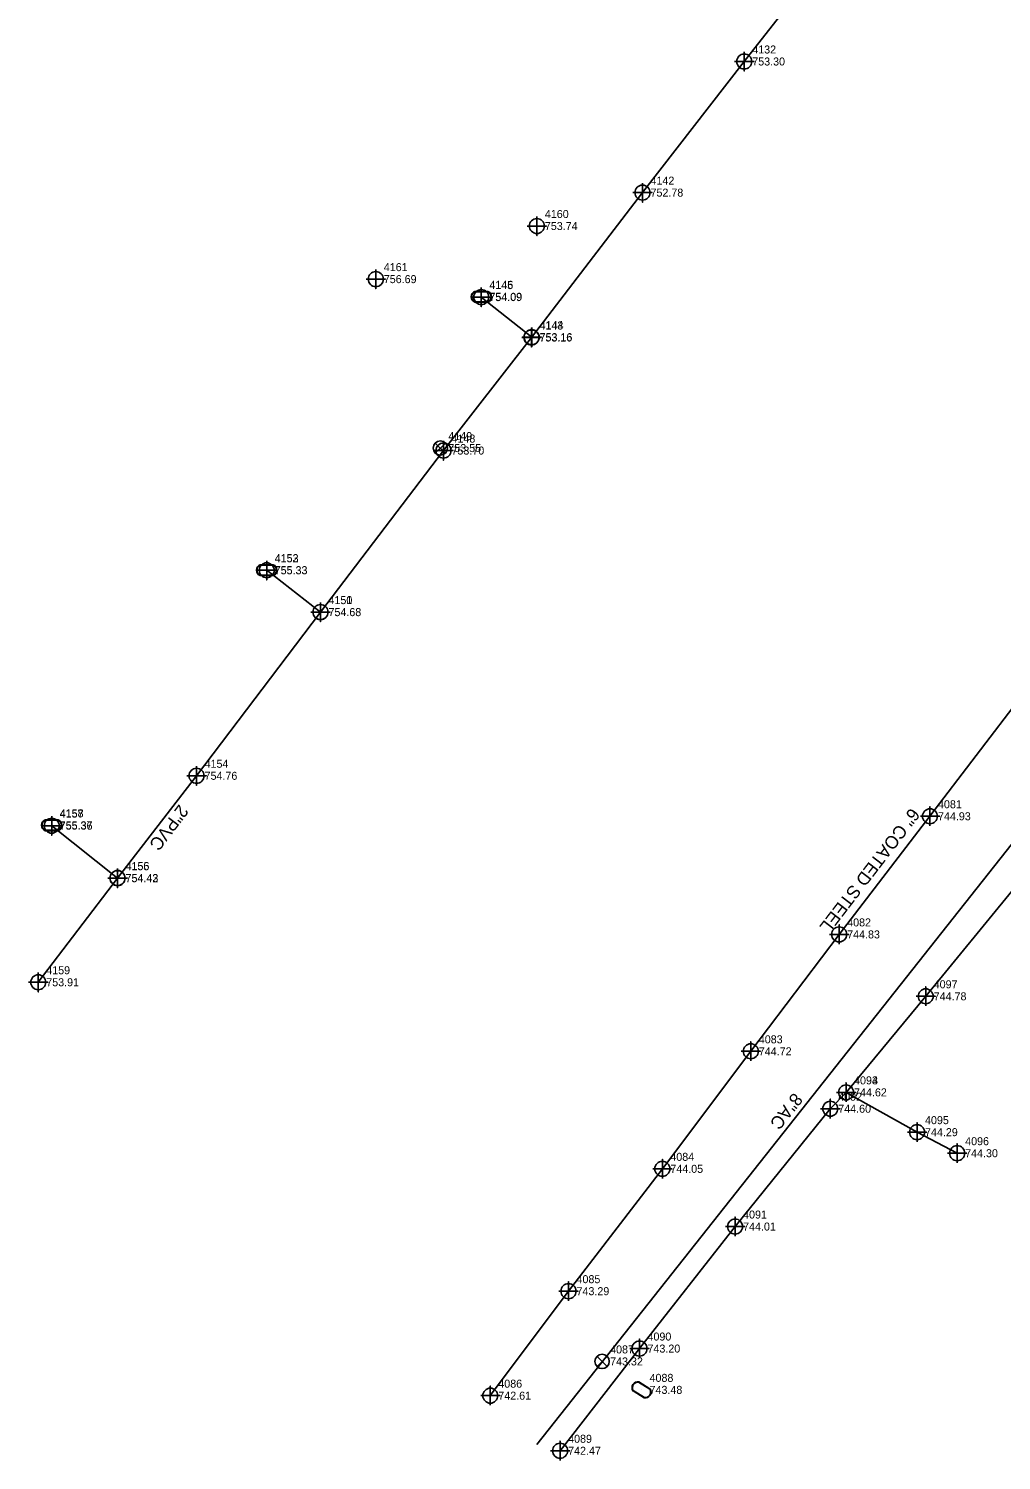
# Model space of a CAD drawing. Extents: x 1622486 to 1624761, y 758733 to 760816.
# Drawn here: x 1622485.7 to 1622789.3, y 758733.4 to 759180.5 of the extents above; entities that cross this region are included whole.
import ezdxf

# ---------------------------------------------------------------- set-up
doc = ezdxf.new("R2010")
doc.units = 0
for name, color, linetype in [('Exist Structure Minor Catch Basin Top Elevation', 7, 'Continuous'), ('Exist Structure Minor Pipes RCP 15 Inch Invert', 7, 'Continuous'), ('Exist Structure Minor Pipes RCP 30 Inch Text', 7, 'Continuous'), ('Exist Utilities Gas UG Line SUE', 7, 'Continuous'), ('Exist Utilities Gas UG Line SUE Cogo Elevation', 7, 'Continuous'), ('Exist Utilities Gas UG Line SUE Cogo Number', 7, 'Continuous'), ('Exist Utilities Gas UG Line SUE Cogo Point CELL', 7, 'Continuous'), ('Exist Utilities Power UG Cable SUE Cogo Elevation', 7, 'Continuous'), ('Exist Utilities Power UG Cable SUE Cogo Number', 7, 'Continuous'), ('Exist Utilities Power UG Cable SUE Cogo Point CELL', 7, 'Continuous'), ('Exist Utilities Water Meter CELL', 7, 'Continuous'), ('Exist Utilities Water Meter Cogo Elevation', 7, 'Continuous'), ('Exist Utilities Water Meter Cogo Number', 7, 'Continuous'), ('Exist Utilities Water UG Line', 7, 'Continuous'), ('Exist Utilities Water UG Line SUE', 7, 'Continuous'), ('Exist Utilities Water UG Line SUE Cogo Elevation', 7, 'Continuous'), ('Exist Utilities Water UG Line SUE Cogo Number', 7, 'Continuous'), ('Exist Utilities Water UG Line SUE Cogo Point CELL', 7, 'Continuous'), ('Exist Utilities Water Valve CELL', 7, 'Continuous'), ('Exist Utilities Water Valve Cogo Elevation', 7, 'Continuous'), ('Exist Utilities Water Valve Cogo Number', 7, 'Continuous')]:
    doc.layers.add(name, color=color, linetype=linetype)

msp = doc.modelspace()

# ---------------------------------------------------------------- linework, layer by layer
at = {"layer": 'Exist Utilities Gas UG Line SUE'}
for points in [[(1622980.39, 759210.11), (1622949.39, 759169.17), (1622919.02, 759130.2), (1622888.55, 759091.6), (1622856.34, 759050.62), (1622825.93, 759011.37), (1622795.93, 758972.46), (1622767.05, 758934.51), (1622738.7, 758897.61), (1622711.11, 758861.1), (1622683.5, 758824.4), (1622654.21, 758786.19), (1622629.8, 758753.56)], [(1622903.04, 759028.02), (1622888.15, 759036.66), (1622851.67, 758988.4), (1622821.78, 758950.05), (1622793.53, 758912.24), (1622765.71, 758878.28), (1622740.85, 758848.28), (1622735.92, 758843.17), (1622706.21, 758806.37), (1622676.37, 758768.27), (1622651.59, 758736.35)], [(1622740.85, 758848.28), (1622763, 758835.85), (1622775.53, 758829.28)]]:
    msp.add_lwpolyline(points, dxfattribs=at)
at = {"layer": 'Exist Utilities Gas UG Line SUE Cogo Point CELL'}
for points in [[(1622764.05, 758934.51), (1622770.05, 758934.51), (1622767.05, 758934.51), (1622767.05, 758937.51), (1622767.05, 758931.51)], [(1622735.7, 758897.61), (1622741.7, 758897.61), (1622738.7, 758897.61), (1622738.7, 758900.61), (1622738.7, 758894.61)], [(1622762.71, 758878.28), (1622768.71, 758878.28), (1622765.71, 758878.28), (1622765.71, 758881.28), (1622765.71, 758875.28)], [(1622708.11, 758861.1), (1622714.11, 758861.1), (1622711.11, 758861.1), (1622711.11, 758864.1), (1622711.11, 758858.1)], [(1622737.85, 758848.28), (1622743.85, 758848.28), (1622740.85, 758848.28), (1622740.85, 758851.28), (1622740.85, 758845.28)], [(1622737.85, 758848.28), (1622743.85, 758848.28), (1622740.85, 758848.28), (1622740.85, 758851.28), (1622740.85, 758845.28)], [(1622732.92, 758843.17), (1622738.92, 758843.17), (1622735.92, 758843.17), (1622735.92, 758846.17), (1622735.92, 758840.17)], [(1622760, 758835.85), (1622766, 758835.85), (1622763, 758835.85), (1622763, 758838.85), (1622763, 758832.85)], [(1622772.53, 758829.28), (1622778.53, 758829.28), (1622775.53, 758829.28), (1622775.53, 758832.28), (1622775.53, 758826.28)], [(1622680.5, 758824.4), (1622686.5, 758824.4), (1622683.5, 758824.4), (1622683.5, 758827.4), (1622683.5, 758821.4)], [(1622703.21, 758806.37), (1622709.21, 758806.37), (1622706.21, 758806.37), (1622706.21, 758809.37), (1622706.21, 758803.37)], [(1622651.21, 758786.19), (1622657.21, 758786.19), (1622654.21, 758786.19), (1622654.21, 758789.19), (1622654.21, 758783.19)], [(1622673.37, 758768.27), (1622679.37, 758768.27), (1622676.37, 758768.27), (1622676.37, 758771.27), (1622676.37, 758765.27)], [(1622626.8, 758753.56), (1622632.8, 758753.56), (1622629.8, 758753.56), (1622629.8, 758756.56), (1622629.8, 758750.56)], [(1622648.59, 758736.35), (1622654.59, 758736.35), (1622651.59, 758736.35), (1622651.59, 758739.35), (1622651.59, 758733.35)]]:
    msp.add_lwpolyline(points, dxfattribs=at)
for centre in [(1622767.05, 758934.51), (1622738.7, 758897.61), (1622765.71, 758878.28), (1622711.11, 758861.1), (1622740.85, 758848.28), (1622740.85, 758848.28), (1622735.92, 758843.17), (1622763, 758835.85), (1622775.53, 758829.28), (1622683.5, 758824.4), (1622706.21, 758806.37), (1622654.21, 758786.19), (1622676.37, 758768.27), (1622629.8, 758753.56), (1622651.59, 758736.35)]:
    msp.add_circle(centre, 2.34, dxfattribs=at)
at = {"layer": 'Exist Utilities Power UG Cable SUE Cogo Point CELL'}
for points in [[(1622644.33, 759121.85), (1622644.33, 759115.85), (1622644.33, 759118.85), (1622647.33, 759118.85), (1622641.33, 759118.85)], [(1622594.05, 759105.26), (1622594.05, 759099.26), (1622594.05, 759102.26), (1622597.05, 759102.26), (1622591.05, 759102.26)]]:
    msp.add_lwpolyline(points, dxfattribs=at)
for centre in [(1622644.33, 759118.85), (1622594.05, 759102.26)]:
    msp.add_circle(centre, 2.34, dxfattribs=at)
at = {"layer": 'Exist Utilities Water Meter CELL'}
for p, q in [((1622627.04, 759096.74), (1622627.04, 759096.74)), ((1622560.01, 759011.37), (1622560.01, 759011.37)), ((1622492.89, 758931.7), (1622492.89, 758931.7)), ((1622677.01, 758755.37), (1622677.01, 758755.37))]:
    msp.add_line(p, q, dxfattribs=at)
for points in [[(1622625, 759098.44), (1622629.07, 759098.44)], [(1622625, 759098.31), (1622629.07, 759098.31)], [(1622629.07, 759095.18), (1622624.97, 759095.18)], [(1622629.07, 759095.04), (1622624.97, 759095.04)], [(1622557.97, 759013.07), (1622562.05, 759013.07)], [(1622557.97, 759012.93), (1622562.05, 759012.93)], [(1622562.05, 759009.81), (1622557.95, 759009.81)], [(1622562.05, 759009.67), (1622557.95, 759009.67)], [(1622494.93, 758930.14), (1622490.83, 758930.14)], [(1622490.86, 758933.4), (1622494.93, 758933.4)], [(1622490.86, 758933.27), (1622494.93, 758933.27)], [(1622494.93, 758930), (1622490.83, 758930)], [(1622676.11, 758757.77), (1622679.56, 758755.61)], [(1622676.18, 758757.89), (1622679.64, 758755.73)], [(1622677.83, 758752.84), (1622674.36, 758755.02)], [(1622677.9, 758752.96), (1622674.43, 758755.14)]]:
    msp.add_lwpolyline(points, dxfattribs=at)
for centre, radius, start, end in [((1622625.73, 759096.74), 1.86, 113.178, 245.9794), ((1622625.74, 759096.74), 1.73, 115.3009, 243.7824), ((1622628.33, 759096.74), 1.86, 293.6483, 66.3084), ((1622628.34, 759096.74), 1.73, 295.1272, 64.8728), ((1622558.7, 759011.36), 1.86, 113.178, 245.9794), ((1622558.71, 759011.36), 1.73, 115.3009, 243.7824), ((1622561.3, 759011.37), 1.86, 293.6483, 66.3084), ((1622561.31, 759011.37), 1.73, 295.1272, 64.8728), ((1622491.59, 758931.7), 1.86, 113.178, 245.9794), ((1622491.6, 758931.7), 1.73, 115.3009, 243.7824), ((1622494.19, 758931.7), 1.86, 293.6483, 66.3084), ((1622494.2, 758931.7), 1.73, 295.1272, 64.8728), ((1622675.9, 758756.05), 1.86, 81.1405, 213.9419), ((1622675.9, 758756.05), 1.73, 83.2634, 211.7448), ((1622678.1, 758754.68), 1.86, 261.6108, 34.2709), ((1622678.11, 758754.67), 1.73, 263.0896, 32.8353)]:
    msp.add_arc(centre, radius, start, end, dxfattribs=at)
at = {"layer": 'Exist Utilities Water UG Line'}
msp.add_lwpolyline([(1622962.92, 759141.34), (1622644.34, 758738.28)], dxfattribs=at)
at = {"layer": 'Exist Utilities Water UG Line SUE'}
for p, q in [((1622626.98, 759096.65), (1622642.71, 759084.14)), ((1622559.99, 759011.32), (1622576.78, 758998.26)), ((1622492.89, 758931.57), (1622513.44, 758915.23))]:
    msp.add_line(p, q, dxfattribs=at)
msp.add_lwpolyline([(1622850.03, 759353.96), (1622834.08, 759332.99), (1622801.51, 759290.71), (1622774.47, 759254.92), (1622731.55, 759198.97), (1622709.07, 759170.23), (1622677.31, 759129.28), (1622642.64, 759084.03), (1622615.18, 759048.72), (1622576.79, 758998.29), (1622538.1, 758947.15), (1622513.42, 758915.16), (1622488.68, 758882.67)], dxfattribs=at)
at = {"layer": 'Exist Utilities Water UG Line SUE Cogo Point CELL'}
for points in [[(1622709.07, 759173.23), (1622709.07, 759167.23), (1622709.07, 759170.23), (1622712.07, 759170.23), (1622706.07, 759170.23)], [(1622677.31, 759132.28), (1622677.31, 759126.28), (1622677.31, 759129.28), (1622680.31, 759129.28), (1622674.31, 759129.28)], [(1622626.98, 759099.65), (1622626.98, 759093.65), (1622626.98, 759096.65), (1622629.98, 759096.65), (1622623.98, 759096.65)], [(1622642.64, 759087.03), (1622642.64, 759081.03), (1622642.64, 759084.03), (1622645.64, 759084.03), (1622639.64, 759084.03)], [(1622642.71, 759087.14), (1622642.71, 759081.14), (1622642.71, 759084.14), (1622645.71, 759084.14), (1622639.71, 759084.14)], [(1622615.18, 759051.72), (1622615.18, 759045.72), (1622615.18, 759048.72), (1622618.18, 759048.72), (1622612.18, 759048.72)], [(1622559.99, 759014.32), (1622559.99, 759008.32), (1622559.99, 759011.32), (1622562.99, 759011.32), (1622556.99, 759011.32)], [(1622576.78, 759001.26), (1622576.78, 758995.26), (1622576.78, 758998.26), (1622579.78, 758998.26), (1622573.78, 758998.26)], [(1622576.79, 759001.29), (1622576.79, 758995.29), (1622576.79, 758998.29), (1622579.79, 758998.29), (1622573.79, 758998.29)], [(1622538.1, 758950.15), (1622538.1, 758944.15), (1622538.1, 758947.15), (1622541.1, 758947.15), (1622535.1, 758947.15)], [(1622492.89, 758934.57), (1622492.89, 758928.57), (1622492.89, 758931.57), (1622495.89, 758931.57), (1622489.89, 758931.57)], [(1622513.42, 758918.16), (1622513.42, 758912.16), (1622513.42, 758915.16), (1622516.42, 758915.16), (1622510.42, 758915.16)], [(1622513.44, 758918.23), (1622513.44, 758912.23), (1622513.44, 758915.23), (1622516.44, 758915.23), (1622510.44, 758915.23)], [(1622488.68, 758885.67), (1622488.68, 758879.67), (1622488.68, 758882.67), (1622491.68, 758882.67), (1622485.68, 758882.67)]]:
    msp.add_lwpolyline(points, dxfattribs=at)
for centre in [(1622709.07, 759170.23), (1622677.31, 759129.28), (1622626.98, 759096.65), (1622642.64, 759084.03), (1622642.71, 759084.14), (1622615.18, 759048.72), (1622559.99, 759011.32), (1622576.78, 758998.26), (1622576.79, 758998.29), (1622538.1, 758947.15), (1622492.89, 758931.57), (1622513.42, 758915.16), (1622513.44, 758915.23), (1622488.68, 758882.67)]:
    msp.add_circle(centre, 2.34, dxfattribs=at)
at = {"layer": 'Exist Utilities Water Valve CELL'}
for points in [[(1622615.78, 759051.07), (1622612.63, 759047.92), (1622614.2, 759049.5), (1622615.78, 759047.92), (1622612.63, 759051.07)], [(1622666.28, 758765.82), (1622663.13, 758762.67), (1622664.7, 758764.25), (1622666.28, 758762.67), (1622663.13, 758765.82)]]:
    msp.add_lwpolyline(points, dxfattribs=at)
for centre in [(1622614.2, 759049.5), (1622664.7, 758764.25)]:
    msp.add_circle(centre, 2.23, dxfattribs=at)

# ---------------------------------------------------------------- texts
at = {"layer": 'Exist Structure Minor Catch Basin Top Elevation'}
msp.add_text('2"PVC', height=4, rotation=232.8858, dxfattribs=at).set_placement((1622532.7, 758938.47))
at = {"layer": 'Exist Structure Minor Pipes RCP 15 Inch Invert'}
msp.add_text('8"AC', height=4, rotation=231.6759, dxfattribs=at).set_placement((1622724.5, 758848.42))
at = {"layer": 'Exist Structure Minor Pipes RCP 30 Inch Text'}
msp.add_text('6" COATED STEEL', height=4, rotation=232.466, dxfattribs=at).set_placement((1622761.04, 758937.38))
at = {"layer": 'Exist Utilities Gas UG Line SUE Cogo Elevation'}
for s, p in [('744.93', (1622769.55, 758933.26)), ('744.83', (1622741.2, 758896.36)), ('744.78', (1622768.21, 758877.03)), ('744.72', (1622713.61, 758859.85)), ('744.62', (1622743.35, 758847.03)), ('744.62', (1622743.35, 758847.03)), ('744.60', (1622738.42, 758841.92)), ('744.29', (1622765.5, 758834.6)), ('744.30', (1622778.03, 758828.03)), ('744.05', (1622686, 758823.15)), ('744.01', (1622708.71, 758805.12)), ('743.29', (1622656.71, 758784.94)), ('743.20', (1622678.87, 758767.02)), ('742.61', (1622632.3, 758752.31)), ('742.47', (1622654.09, 758735.1))]:
    msp.add_text(s, height=2.5, dxfattribs=at).set_placement(p)
at = {"layer": 'Exist Utilities Gas UG Line SUE Cogo Number'}
for s, p in [('4081', (1622769.55, 758937.01)), ('4082', (1622741.2, 758900.11)), ('4097', (1622768.21, 758880.78)), ('4083', (1622713.61, 758863.6)), ('4093', (1622743.35, 758850.78)), ('4094', (1622743.35, 758850.78)), ('4092', (1622738.42, 758845.67)), ('4095', (1622765.5, 758838.35)), ('4096', (1622778.03, 758831.78)), ('4084', (1622686, 758826.9)), ('4091', (1622708.71, 758808.87)), ('4085', (1622656.71, 758788.69)), ('4090', (1622678.87, 758770.77)), ('4086', (1622632.3, 758756.06)), ('4089', (1622654.09, 758738.85))]:
    msp.add_text(s, height=2.5, dxfattribs=at).set_placement(p)
at = {"layer": 'Exist Utilities Power UG Cable SUE Cogo Elevation'}
for s, p in [('753.74', (1622646.83, 759117.6)), ('756.69', (1622596.55, 759101.01))]:
    msp.add_text(s, height=2.5, dxfattribs=at).set_placement(p)
at = {"layer": 'Exist Utilities Power UG Cable SUE Cogo Number'}
for s, p in [('4160', (1622646.83, 759121.35)), ('4161', (1622596.55, 759104.76))]:
    msp.add_text(s, height=2.5, dxfattribs=at).set_placement(p)
at = {"layer": 'Exist Utilities Water Meter Cogo Elevation'}
for s, p in [('754.09', (1622629.54, 759095.49)), ('755.33', (1622562.51, 759010.12)), ('755.37', (1622495.39, 758930.45)), ('743.48', (1622679.51, 758754.12))]:
    msp.add_text(s, height=2.5, dxfattribs=at).set_placement(p)
at = {"layer": 'Exist Utilities Water Meter Cogo Number'}
for s, p in [('4146', (1622629.54, 759099.24)), ('4153', (1622562.51, 759013.87)), ('4158', (1622495.39, 758934.2)), ('4088', (1622679.51, 758757.87))]:
    msp.add_text(s, height=2.5, dxfattribs=at).set_placement(p)
at = {"layer": 'Exist Utilities Water UG Line SUE Cogo Elevation'}
for s, p in [('753.30', (1622711.57, 759168.98)), ('752.78', (1622679.81, 759128.03)), ('754.09', (1622629.48, 759095.4)), ('753.16', (1622645.14, 759082.78)), ('753.16', (1622645.21, 759082.89)), ('753.70', (1622617.68, 759047.47)), ('755.33', (1622562.49, 759010.07)), ('754.68', (1622579.28, 758997.01)), ('754.68', (1622579.29, 758997.04)), ('754.76', (1622540.6, 758945.9)), ('755.36', (1622495.39, 758930.32)), ('754.42', (1622515.92, 758913.91)), ('754.43', (1622515.94, 758913.98)), ('753.91', (1622491.18, 758881.42))]:
    msp.add_text(s, height=2.5, dxfattribs=at).set_placement(p)
at = {"layer": 'Exist Utilities Water UG Line SUE Cogo Number'}
for s, p in [('4132', (1622711.57, 759172.73)), ('4142', (1622679.81, 759131.78)), ('4145', (1622629.48, 759099.15)), ('4143', (1622645.14, 759086.53)), ('4144', (1622645.21, 759086.64)), ('4148', (1622617.68, 759051.22)), ('4152', (1622562.49, 759013.82)), ('4151', (1622579.28, 759000.76)), ('4150', (1622579.29, 759000.79)), ('4154', (1622540.6, 758949.65)), ('4157', (1622495.39, 758934.07)), ('4155', (1622515.92, 758917.66)), ('4156', (1622515.94, 758917.73)), ('4159', (1622491.18, 758885.17))]:
    msp.add_text(s, height=2.5, dxfattribs=at).set_placement(p)
at = {"layer": 'Exist Utilities Water Valve Cogo Elevation'}
for s, p in [('753.55', (1622616.7, 759048.25)), ('743.32', (1622667.2, 758763))]:
    msp.add_text(s, height=2.5, dxfattribs=at).set_placement(p)
at = {"layer": 'Exist Utilities Water Valve Cogo Number'}
for s, p in [('4149', (1622616.7, 759052)), ('4087', (1622667.2, 758766.75))]:
    msp.add_text(s, height=2.5, dxfattribs=at).set_placement(p)

doc.saveas('drawing.dxf')
